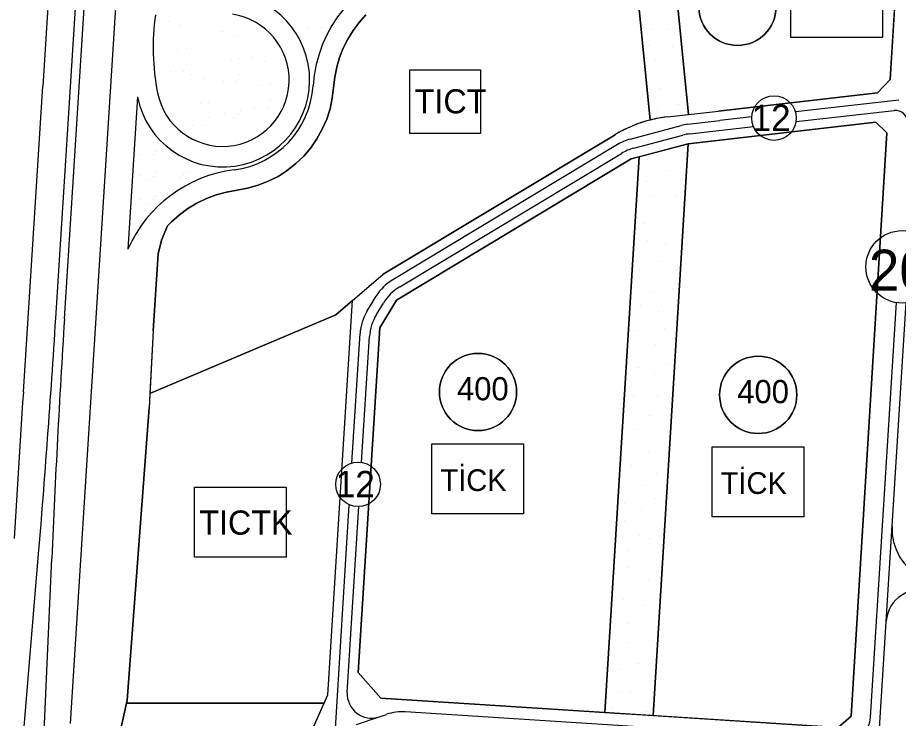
# Model space of a CAD drawing. Extents: x 419109 to 421295, y 4452223 to 4457798.
# Drawn here: x 420098 to 420462.6, y 4453421.6 to 4453711.7 of the extents above; entities that cross this region are included whole.
import ezdxf

# ---------------------------------------------------------------- set-up
doc = ezdxf.new("R2010")
doc.units = 0
for name, color, linetype in [('ADA', 7, 'Continuous'), ('ADAKENARI', 7, 'Continuous'), ('Default', 7, 'Continuous'), ('KALDIRIM', 7, 'Continuous'), ('KD_DAIRE', 7, 'Continuous'), ('KD_YGEN', 7, 'Continuous'), ('LJ_SEMBOL', 7, 'Continuous'), ('PL_AYA_PARK_DINLENME', 7, 'Continuous'), ('PL_BAKIM_AKARYAKIT', 7, 'Continuous'), ('PL_TİCK', 7, 'Continuous'), ('PL_TİCT', 7, 'Continuous'), ('PL_TURZM', 7, 'Continuous'), ('RAYLI_TOPLU_TAŞIMA_HATTI', 7, 'Continuous'), ('SM_TAKS', 7, 'Continuous'), ('TR_BAKIMAKARYAKIT', 7, 'Continuous'), ('TR_PARKALANI', 7, 'Continuous'), ('TR_TİC_TURIZM_K', 7, 'Continuous'), ('TR_TİCK', 7, 'Continuous'), ('TR_TİCT', 7, 'Continuous')]:
    doc.layers.add(name, color=color, linetype=linetype)

# ---------------------------------------------------------------- blocks, each defined once
blk = doc.blocks.new('POINT_DISPLAY')
at = {"layer": 'Default'}
blk.add_line((0, 0), (0, 0), dxfattribs=at)

msp = doc.modelspace()

# ---------------------------------------------------------------- linework, layer by layer
at = {"layer": 'ADA'}
msp.add_line((420152.72, 4453556.08), (420229.75, 4453588.65), dxfattribs=at)
at = {"layer": 'ADAKENARI'}
for p, q in [((420462.36, 4453737.04), (420459.23, 4453686.05)), ((420239.35, 4453709.68), (420242.14, 4453712.81)), ((420236.85, 4453706.32), (420239.35, 4453709.68)), ((420234.66, 4453702.75), (420236.85, 4453706.32)), ((420232.79, 4453699), (420234.66, 4453702.75)), ((420231.26, 4453695.11), (420232.79, 4453699)), ((420230.07, 4453691.09), (420231.26, 4453695.11)), ((420229.25, 4453686.98), (420230.07, 4453691.09)), ((420228.77, 4453682.7), (420229.25, 4453686.98)), ((420453.95, 4453680.49), (420459.23, 4453686.05)), ((420228.26, 4453678.33), (420228.77, 4453682.7)), ((420453.95, 4453680.49), (420388.2, 4453673)), ((420227.31, 4453673.91), (420228.26, 4453678.33)), ((420225.92, 4453669.6), (420227.31, 4453673.91)), ((420367.01, 4453670.59), (420388.2, 4453673)), ((420224.11, 4453665.46), (420225.92, 4453669.6)), ((420375.53, 4453659.48), (420453.21, 4453668.33)), ((420453.21, 4453668.33), (420457.87, 4453663.91)), ((420221.91, 4453661.5), (420224.11, 4453665.46)), ((420219.33, 4453657.79), (420221.91, 4453661.5)), ((420345.29, 4453663.2), (420249.28, 4453605.42)), ((420457.87, 4453663.91), (420443, 4453422.53)), ((420216.4, 4453654.35), (420219.33, 4453657.79)), ((420351.94, 4453653.2), (420375.53, 4453659.48)), ((420361.03, 4453422.74), (420375.53, 4453659.48)), ((420213.14, 4453651.21), (420216.4, 4453654.35)), ((420355.23, 4453654.08), (420341.07, 4453424.01)), ((420209.59, 4453648.4), (420213.14, 4453651.21)), ((420254.85, 4453594.77), (420351.94, 4453653.2)), ((420205.78, 4453645.96), (420209.59, 4453648.4)), ((420197.54, 4453642.26), (420201.75, 4453643.91)), ((420201.75, 4453643.91), (420205.78, 4453645.96)), ((420180.22, 4453638.33), (420184.43, 4453639.48)), ((420184.43, 4453639.48), (420188.86, 4453640.25)), ((420188.86, 4453640.25), (420193.19, 4453641.03)), ((420193.19, 4453641.03), (420197.54, 4453642.26)), ((420172.19, 4453634.9), (420176.13, 4453636.8)), ((420176.13, 4453636.8), (420180.22, 4453638.33)), ((420164.93, 4453630.06), (420168.45, 4453632.65)), ((420168.45, 4453632.65), (420172.19, 4453634.9)), ((420161.66, 4453627.16), (420164.93, 4453630.06)), ((420157.53, 4453619.58), (420160.07, 4453625.47)), ((420160.07, 4453625.47), (420161.66, 4453627.16)), ((420156.15, 4453613.84), (420157.53, 4453619.58)), ((420154.15, 4453582.04), (420156.15, 4453613.84)), ((420229.75, 4453588.65), (420249.28, 4453605.42)), ((420226.37, 4453431.32), (420236.57, 4453594.51)), ((420247.89, 4453583.31), (420254.85, 4453594.77)), ((420152.72, 4453556.08), (420229.75, 4453588.65)), ((420154.15, 4453582.04), (420152.39, 4453550.07)), ((420238.97, 4453440.53), (420247.89, 4453583.31)), ((420143.3, 4453429.09), (420152.39, 4453550.07)), ((420248.32, 4453429.92), (420238.97, 4453440.53)), ((420201.75, 4453375.93), (420226.37, 4453431.32)), ((420140.52, 4453416.74), (420143.3, 4453429.09)), ((420224.86, 4453427.92), (420143.04, 4453427.92)), ((420437.71, 4453417.85), (420248.32, 4453429.92)), ((420443, 4453422.53), (420437.71, 4453417.85))]:
    msp.add_line(p, q, dxfattribs=at)
for points in [[(420368.42, 4453744.92), (420369.63, 4453732.7), (420375.68, 4453671.57)], [(420352.63, 4453742.02), (420352.8, 4453740.33), (420359.83, 4453669.27)], [(420147.58, 4453678.81), (420143.61, 4453615.87)]]:
    msp.add_lwpolyline(points, dxfattribs=at)
for centre, radius, start, end in [((420276.18, 4453679.68), 56, 104.3618, 176.2103), ((420182.88, 4453685.86), 36, 191.2883, 91.5799), ((420251.58, 4453699.33), 97.5, 172.0136, 191.0918), ((420182.88, 4453685.86), 27.5, 191.0918, 81.5916), ((420182.88, 4453685.86), 37.5, 277.3124, 356.2103), ((420373.13, 4453616.93), 54, 96.5014, 121.0389), ((420194.78, 4453593.12), 56, 97.3124, 156.0301)]:
    msp.add_arc(centre, radius, start, end, dxfattribs=at)
at = {"layer": 'KALDIRIM'}
for p, q in [((420111.94, 4453738.78), (420110.08, 4453709.57)), ((420140.12, 4453740.77), (420138.26, 4453711.56)), ((420110.08, 4453709.57), (420108.4, 4453683.29)), ((420138.26, 4453711.56), (420121.18, 4453443.53)), ((420100.34, 4453556.74), (420108.4, 4453683.29)), ((420462.85, 4453677.48), (420419.99, 4453672.6)), ((420420.23, 4453668.6), (420460.84, 4453673.23)), ((420375.5, 4453667.53), (420388.65, 4453669.03)), ((420401.9, 4453670.54), (420388.65, 4453669.03)), ((420351.53, 4453661.37), (420372.62, 4453666.98)), ((420376.24, 4453663.59), (420402.58, 4453666.59)), ((420353.1, 4453657.65), (420373.36, 4453663.04)), ((420346.36, 4453659.18), (420253.26, 4453603.15)), ((420256.17, 4453600.23), (420347.93, 4453655.46)), ((420242.59, 4453589.99), (420246.48, 4453596.4)), ((420246.52, 4453588.76), (420249.38, 4453593.48)), ((420451.08, 4453422.03), (420461.77, 4453593.69)), ((420460.03, 4453501.31), (420465.77, 4453593.59)), ((420236.38, 4453527.33), (420239.72, 4453580.86)), ((420240.4, 4453527.58), (420243.65, 4453579.63)), ((420100.34, 4453556.74), (420100.06, 4453552.29)), ((420100.06, 4453552.29), (420096.48, 4453496.11)), ((420229.51, 4453417.45), (420235.29, 4453510)), ((420234.45, 4453432.31), (420239.25, 4453509.25)), ((420445.72, 4453271.49), (420460.03, 4453501.31)), ((420121.18, 4453443.53), (420119.66, 4453419.53)), ((420440.47, 4453412.67), (420258.4, 4453424.27)), ((420238.25, 4453419.06), (420247.61, 4453422.21)), ((420247.61, 4453422.21), (420250.75, 4453423.26))]:
    msp.add_line(p, q, dxfattribs=at)
for centre, radius, start, end in [((420461.4, 4453668.26), 5, 356.4375, 96.5014), ((420377.76, 4453647.66), 20, 96.5014, 104.9038), ((420356.67, 4453642.04), 20, 104.9038, 121.0392), ((420378.51, 4453643.71), 20, 96.5014, 104.9038), ((420358.25, 4453638.32), 20, 104.9038, 121.0392), ((420263.57, 4453586.01), 20, 121.0392, 148.7317), ((420266.48, 4453583.1), 20, 121.0392, 148.7317), ((420259.68, 4453579.61), 20, 148.7317, 176.4243), ((420263.61, 4453578.38), 20, 148.7317, 176.4243), ((420482.24, 4453499.92), 22.26, 176.4375, 245.1603), ((420471.28, 4453460.92), 13.74, 65.1603, 176.4375), ((420244.43, 4453431.69), 10, 176.4243, 288.5824), ((420257.12, 4453404.31), 20, 86.3557, 108.5824), ((420441.1, 4453422.65), 10, 266.3557, 356.4375)]:
    msp.add_arc(centre, radius, start, end, dxfattribs=at)
at = {"layer": 'KD_DAIRE'}
for centre, radius in [((420411.12, 4453670.07), 9.23), ((420464.15, 4453608.5), 15), ((420238.95, 4453518.47), 9.23)]:
    msp.add_circle(centre, radius, dxfattribs=at)
at = {"layer": 'LJ_SEMBOL'}
for points in [[(420418.07, 4453732.3), (420456, 4453732.3), (420456, 4453703.37), (420418.07, 4453703.37)], [(420260.34, 4453690.09), (420289.54, 4453690.09), (420289.54, 4453663.73), (420260.34, 4453663.73)], [(420269.49, 4453535.19), (420307.42, 4453535.19), (420307.42, 4453506.26), (420269.49, 4453506.26)], [(420385.51, 4453534.01), (420423.44, 4453534.01), (420423.44, 4453505.07), (420385.51, 4453505.07)], [(420171.16, 4453517.26), (420209.09, 4453517.26), (420209.09, 4453488.32), (420171.16, 4453488.32)]]:
    msp.add_lwpolyline(points, close=True, dxfattribs=at)
at = {"layer": 'PL_AYA_PARK_DINLENME'}
for points in [[(420367.01, 4453670.59), (420375.68, 4453671.57), (420369.63, 4453732.7), (420368.42, 4453744.92), (420352.63, 4453742.02), (420352.8, 4453740.33), (420359.83, 4453669.27)], [(420147.58, 4453678.81), (420143.61, 4453615.87)], [(420341.07, 4453424.01), (420361.03, 4453422.74), (420375.53, 4453659.48), (420355.23, 4453654.08), (420341.07, 4453424.01)]]:
    msp.add_lwpolyline(points, dxfattribs=at)
for centre, radius, start, end in [((420276.18, 4453679.68), 56, 104.3618, 176.2103), ((420182.88, 4453685.86), 36, 191.2883, 91.5799), ((420251.58, 4453699.33), 97.5, 172.0136, 191.0918), ((420182.88, 4453685.86), 27.5, 191.0918, 81.5916), ((420182.88, 4453685.86), 37.5, 277.3124, 356.2103), ((420373.13, 4453616.93), 54, 96.5014, 104.258), ((420194.78, 4453593.12), 56, 97.3124, 156.0301)]:
    msp.add_arc(centre, radius, start, end, dxfattribs=at)
at = {"layer": 'PL_BAKIM_AKARYAKIT'}
msp.add_lwpolyline([(420143.04, 4453427.92), (420140.52, 4453416.74), (420137.29, 4453367.44), (420201.05, 4453367.44), (420201.75, 4453375.93), (420224.86, 4453427.92), (420143.04, 4453427.92)], dxfattribs=at)
at = {"layer": 'PL_TİCK'}
for points in [[(420438.42, 4453758.01), (420412.32, 4453752.98), (420378.31, 4453746.73), (420368.42, 4453744.92), (420369.63, 4453732.7), (420375.68, 4453671.57)], [(420375.68, 4453671.57), (420388.2, 4453673), (420453.95, 4453680.49), (420459.23, 4453686.05), (420462.36, 4453737.04), (420462.16, 4453739.85)], [(420361.03, 4453422.74), (420437.71, 4453417.85), (420443, 4453422.53), (420457.87, 4453663.91), (420453.21, 4453668.33), (420375.53, 4453659.48), (420361.03, 4453422.74)], [(420355.23, 4453654.08), (420351.94, 4453653.2), (420254.85, 4453594.77), (420247.89, 4453583.31), (420238.97, 4453440.53), (420248.32, 4453429.92), (420341.07, 4453424.01), (420355.23, 4453654.08)]]:
    msp.add_lwpolyline(points, dxfattribs=at)
at = {"layer": 'PL_TİCT'}
for points in [[(420359.83, 4453669.27), (420352.8, 4453740.33)], [(420242.14, 4453712.81), (420239.35, 4453709.68), (420236.85, 4453706.32), (420234.66, 4453702.75), (420232.79, 4453699), (420231.26, 4453695.11), (420230.07, 4453691.09), (420229.25, 4453686.98), (420228.77, 4453682.7), (420228.26, 4453678.33), (420227.31, 4453673.91), (420225.92, 4453669.6), (420224.11, 4453665.46), (420221.91, 4453661.5), (420219.33, 4453657.79), (420216.4, 4453654.35), (420213.14, 4453651.21), (420209.59, 4453648.4), (420205.78, 4453645.96), (420201.75, 4453643.91), (420197.54, 4453642.26), (420193.19, 4453641.03), (420188.86, 4453640.25), (420184.43, 4453639.48), (420180.22, 4453638.33), (420176.13, 4453636.8), (420172.19, 4453634.9), (420168.45, 4453632.65), (420164.93, 4453630.06), (420161.66, 4453627.16), (420160.07, 4453625.47), (420157.53, 4453619.58), (420156.15, 4453613.84), (420154.15, 4453582.04), (420152.72, 4453556.08), (420229.75, 4453588.65), (420236.57, 4453594.51), (420249.28, 4453605.42), (420345.29, 4453663.2)]]:
    msp.add_lwpolyline(points, dxfattribs=at)
msp.add_arc((420373.13, 4453616.93), 54, 104.258, 121.0389, dxfattribs=at)
at = {"layer": 'PL_TURZM'}
msp.add_lwpolyline([(420224.86, 4453427.92), (420226.37, 4453431.32), (420236.57, 4453594.51), (420229.75, 4453588.65), (420152.72, 4453556.08), (420152.39, 4453550.07), (420143.3, 4453429.09), (420143.04, 4453427.92), (420224.86, 4453427.92)], dxfattribs=at)
at = {"layer": 'RAYLI_TOPLU_TAŞIMA_HATTI'}
for p, q in [((420113.77, 4453587.19), (420124.29, 4453754.1)), ((420117.36, 4453586.97), (420127.88, 4453753.87)), ((420099.85, 4453407.54), (420106.54, 4453488.11)), ((420108.62, 4453406.99), (420112.1, 4453487.76))]:
    msp.add_line(p, q, dxfattribs=at)
for centre, start, end in [((415123.67, 4453901.65), 355.25584, 356.39423), ((425107.47, 4453272.51), 176.39423, 177.53262)]:
    msp.add_arc(centre, 5000, start, end, dxfattribs=at)
at = {"layer": 'SM_TAKS'}
for centre in [(420396, 4453716.14), (420288.56, 4453556.7), (420404.58, 4453555.51)]:
    msp.add_circle(centre, 15.99, dxfattribs=at)
at = {"layer": 'TR_BAKIMAKARYAKIT'}
msp.add_lwpolyline([(420143.04, 4453427.92), (420140.52, 4453416.74), (420137.29, 4453367.44), (420201.05, 4453367.44), (420201.75, 4453375.93), (420224.86, 4453427.92), (420143.04, 4453427.92)], dxfattribs=at)
at = {"layer": 'TR_TİC_TURIZM_K'}
for points in [[(420152.72, 4453556.08), (420152.39, 4453550.07), (420143.3, 4453429.09), (420143.04, 4453427.92), (420224.86, 4453427.92), (420226.37, 4453431.32), (420236.57, 4453594.51), (420229.75, 4453588.65), (420152.72, 4453556.08)], [(420171.16, 4453488.32), (420171.16, 4453517.26), (420209.09, 4453517.26), (420209.09, 4453488.32), (420171.16, 4453488.32)]]:
    msp.add_lwpolyline(points, dxfattribs=at)
at = {"layer": 'TR_TİCK'}
for points in [[(420369.63, 4453732.7), (420375.68, 4453671.57), (420388.2, 4453673), (420453.95, 4453680.49), (420459.23, 4453686.05), (420462.36, 4453737.04), (420462.16, 4453739.85)], [(420418.07, 4453703.37), (420418.07, 4453732.3), (420456, 4453732.3), (420456, 4453703.37), (420418.07, 4453703.37)], [(420457.87, 4453663.91), (420453.21, 4453668.33), (420375.53, 4453659.48), (420361.03, 4453422.74), (420437.71, 4453417.85), (420443, 4453422.53), (420457.87, 4453663.91)], [(420355.23, 4453654.08), (420351.94, 4453653.2), (420254.85, 4453594.77), (420247.89, 4453583.31), (420238.97, 4453440.53), (420248.32, 4453429.92), (420341.07, 4453424.01), (420355.23, 4453654.08)], [(420269.49, 4453506.26), (420269.49, 4453535.19), (420307.42, 4453535.19), (420307.42, 4453506.26), (420269.49, 4453506.26)], [(420385.51, 4453505.07), (420385.51, 4453534.01), (420423.44, 4453534.01), (420423.44, 4453505.07), (420385.51, 4453505.07)]]:
    msp.add_lwpolyline(points, dxfattribs=at)
for centre, start, end in [((420396, 4453716.14), 180, 0), ((420288.56, 4453556.7), 0, 180), ((420404.58, 4453555.51), 0, 180), ((420288.56, 4453556.7), 180, 0), ((420404.58, 4453555.51), 180, 0)]:
    msp.add_arc(centre, 15.99, start, end, dxfattribs=at)
at = {"layer": 'TR_TİCT'}
for points in [[(420359.83, 4453669.27), (420352.8, 4453740.33)], [(420242.14, 4453712.81), (420239.35, 4453709.68), (420236.85, 4453706.32), (420234.66, 4453702.75), (420232.79, 4453699), (420231.26, 4453695.11), (420230.07, 4453691.09), (420229.25, 4453686.98), (420228.77, 4453682.7), (420228.26, 4453678.33), (420227.31, 4453673.91), (420225.92, 4453669.6), (420224.11, 4453665.46), (420221.91, 4453661.5), (420219.33, 4453657.79), (420216.4, 4453654.35), (420213.14, 4453651.21), (420209.59, 4453648.4), (420205.78, 4453645.96), (420201.75, 4453643.91), (420197.54, 4453642.26), (420193.19, 4453641.03), (420188.86, 4453640.25), (420184.43, 4453639.48), (420180.22, 4453638.33), (420176.13, 4453636.8), (420172.19, 4453634.9), (420168.45, 4453632.65), (420164.93, 4453630.06), (420161.66, 4453627.16), (420160.07, 4453625.47), (420157.53, 4453619.58), (420156.15, 4453613.84), (420154.15, 4453582.04), (420152.72, 4453556.08), (420229.75, 4453588.65), (420236.57, 4453594.51), (420249.28, 4453605.42), (420345.29, 4453663.2)], [(420260.34, 4453663.73), (420260.34, 4453690.09), (420289.54, 4453690.09), (420289.54, 4453663.73), (420260.34, 4453663.73)]]:
    msp.add_lwpolyline(points, dxfattribs=at)
msp.add_arc((420373.13, 4453616.93), 54, 104.258, 121.0389, dxfattribs=at)

# ---------------------------------------------------------------- block references
at = {"layer": 'TR_PARKALANI', "xscale": 0.1, "yscale": 0.10000000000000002}
for p in [(420160.61, 4453710.04), (420165.6, 4453708.44), (420222, 4453711.58), (420182.73, 4453705.87), (420218.22, 4453707.57), (420222, 4453706.15), (420223.71, 4453707.5), (420228.1, 4453707.65), (420228.62, 4453707.57), (420360.5, 4453706.58), (420367.53, 4453706.73), (420187.72, 4453704.27), (420164.33, 4453698.35), (420167.88, 4453698.77), (420359.31, 4453700.22), (420369.23, 4453699.63), (420186.45, 4453694.17), (420190, 4453694.6), (420195.36, 4453695.19), (420167.87, 4453692.36), (420200.36, 4453693.59), (420361.98, 4453693.71), (420161.11, 4453689.29), (420166.6, 4453689.22), (420169.79, 4453687.92), (420190, 4453688.19), (420369.97, 4453688.38), (420174.78, 4453686.32), (420183.23, 4453685.12), (420188.72, 4453685.04), (420199.08, 4453683.5), (420202.63, 4453683.92), (420364.05, 4453682.17), (420173.51, 4453676.23), (420177.06, 4453676.65), (420202.63, 4453677.52), (420190.3, 4453673.2), (420195.86, 4453674.44), (420201.35, 4453674.37), (420362.86, 4453673.14), (420371.59, 4453675.51), (420177.06, 4453670.24), (420183.68, 4453671.78), (420187.46, 4453670.36), (420189.17, 4453671.71), (420170.29, 4453667.17), (420175.78, 4453667.1), (420148.62, 4453654.88), (420154.11, 4453654.8), (420155.24, 4453656.3), (420152.41, 4453653.46), (420358.72, 4453652.79), (420155.24, 4453647.53), (420161.14, 4453646.74), (420166.64, 4453646.67), (420167.76, 4453648.16), (420367.75, 4453648.2), (420148.62, 4453646.11), (420152.41, 4453644.69), (420154.11, 4453646.04), (420164.93, 4453645.32), (420358.42, 4453643.91), (420148.62, 4453636.3), (420154.11, 4453636.23), (420155.24, 4453637.72), (420359.9, 4453637.7), (420370.56, 4453637.7), (420152.41, 4453634.89), (420366.42, 4453628.97), (420356.94, 4453626.45), (420358.72, 4453619.2), (420366.12, 4453617.87), (420364.34, 4453610.76), (420355.32, 4453607.06), (420370.26, 4453606.92), (420369.23, 4453599.22), (420361.09, 4453598.19), (420355.76, 4453592.41), (420363.46, 4453589.9), (420353.39, 4453582.13), (420365.82, 4453582.94), (420362.12, 4453576.43), (420355.02, 4453566.66), (420367.75, 4453568.14), (420361.68, 4453564), (420353.1, 4453555.42), (420362.72, 4453555.42), (420359.61, 4453547.13), (420353.54, 4453541.21), (420365.68, 4453535.44), (420359.31, 4453532.04), (420352.06, 4453526.26), (420362.42, 4453523.16), (420356.65, 4453517.83), (420361.98, 4453512.5), (420349.1, 4453510.43), (420356.35, 4453507.77), (420349.25, 4453503.62), (420355.46, 4453497.11), (420359.46, 4453495.93), (420350.73, 4453490.9), (420350.28, 4453484.09), (420359.16, 4453478.76), (420348.95, 4453470.92), (420357.68, 4453468.11), (420351.02, 4453460.71), (420350.28, 4453453.16), (420361.24, 4453453.9), (420355.17, 4453444.13), (420347.03, 4453441.62), (420359.61, 4453439.69), (420346.59, 4453432.59), (420351.76, 4453432.29), (420343.92, 4453426.08), (420358.42, 4453424.3)]:
    msp.add_blockref('POINT_DISPLAY', p, dxfattribs=at)

# ---------------------------------------------------------------- texts
at = {"layer": 'KD_YGEN'}
for s, height, p in [('12', 10.905, (420401.81, 4453664.71)), ('20', 17, (420450.39, 4453598.6)), ('12', 10.905, (420229.64, 4453513.11))]:
    msp.add_text(s, height=height, dxfattribs=at).set_placement(p)
at = {"layer": 'LJ_SEMBOL'}
for s, height, p in [('TICT', 10, (420262.36, 4453672.02)), ('TİCK', 9, (420273.01, 4453515.69)), ('TİCK', 9, (420389.03, 4453514.5)), ('TICTK', 10, (420173.18, 4453497.64))]:
    msp.add_text(s, height=height, dxfattribs=at).set_placement(p)
at = {"layer": 'SM_TAKS'}
for p in [(420279.87, 4453553.25), (420395.89, 4453552.06)]:
    msp.add_text('400', height=9.593, dxfattribs=at).set_placement(p)

doc.saveas('drawing.dxf')
